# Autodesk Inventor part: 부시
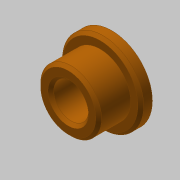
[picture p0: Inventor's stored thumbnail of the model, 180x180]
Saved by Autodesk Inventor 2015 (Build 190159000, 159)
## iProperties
Created: 2016-02
Part Number: 부시
Material: 강철, 연강
Document SubType Name: Modeling
Designer: test
Density: 1 g/cm^3
Appearance: 주황색
Author: test
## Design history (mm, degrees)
sketch "스케치1"
  geometry: C1 r 14 at (0, 0); C2 r 10.5 at (0, 0); 1 further point
  constraints: 2 centre point, 2 coincident
  dimensions: "d0" = 28 diameter of C1; "d1" = 21 diameter of C2
extrude "돌출1" new body sketch "스케치1" distance "d2" = 4; taper "d3" = 0 deg
extrude "돌출2" join sketch "스케치1" distance "d4" = 11; taper "d5" = 0 deg
hole "구멍1" diameter "d8" = 12; stored, may be unused: countersink angle "d12" = 90 deg, drill point angle "d14" = 118 deg; dims "d6" = 10, "d7" = 10, "d9" = 6, "d10" = 4, "d11" = 2, "d13" = 8
chamfer "모따기1" distance "d15" = 1; stored, may be unused: second distance "d16" = 2, angle "d17" = 45 deg
chamfer "모따기2" distance "d18" = 1; stored, may be unused: second distance "d19" = 2, angle "d20" = 45 deg
node "솔리드1"
